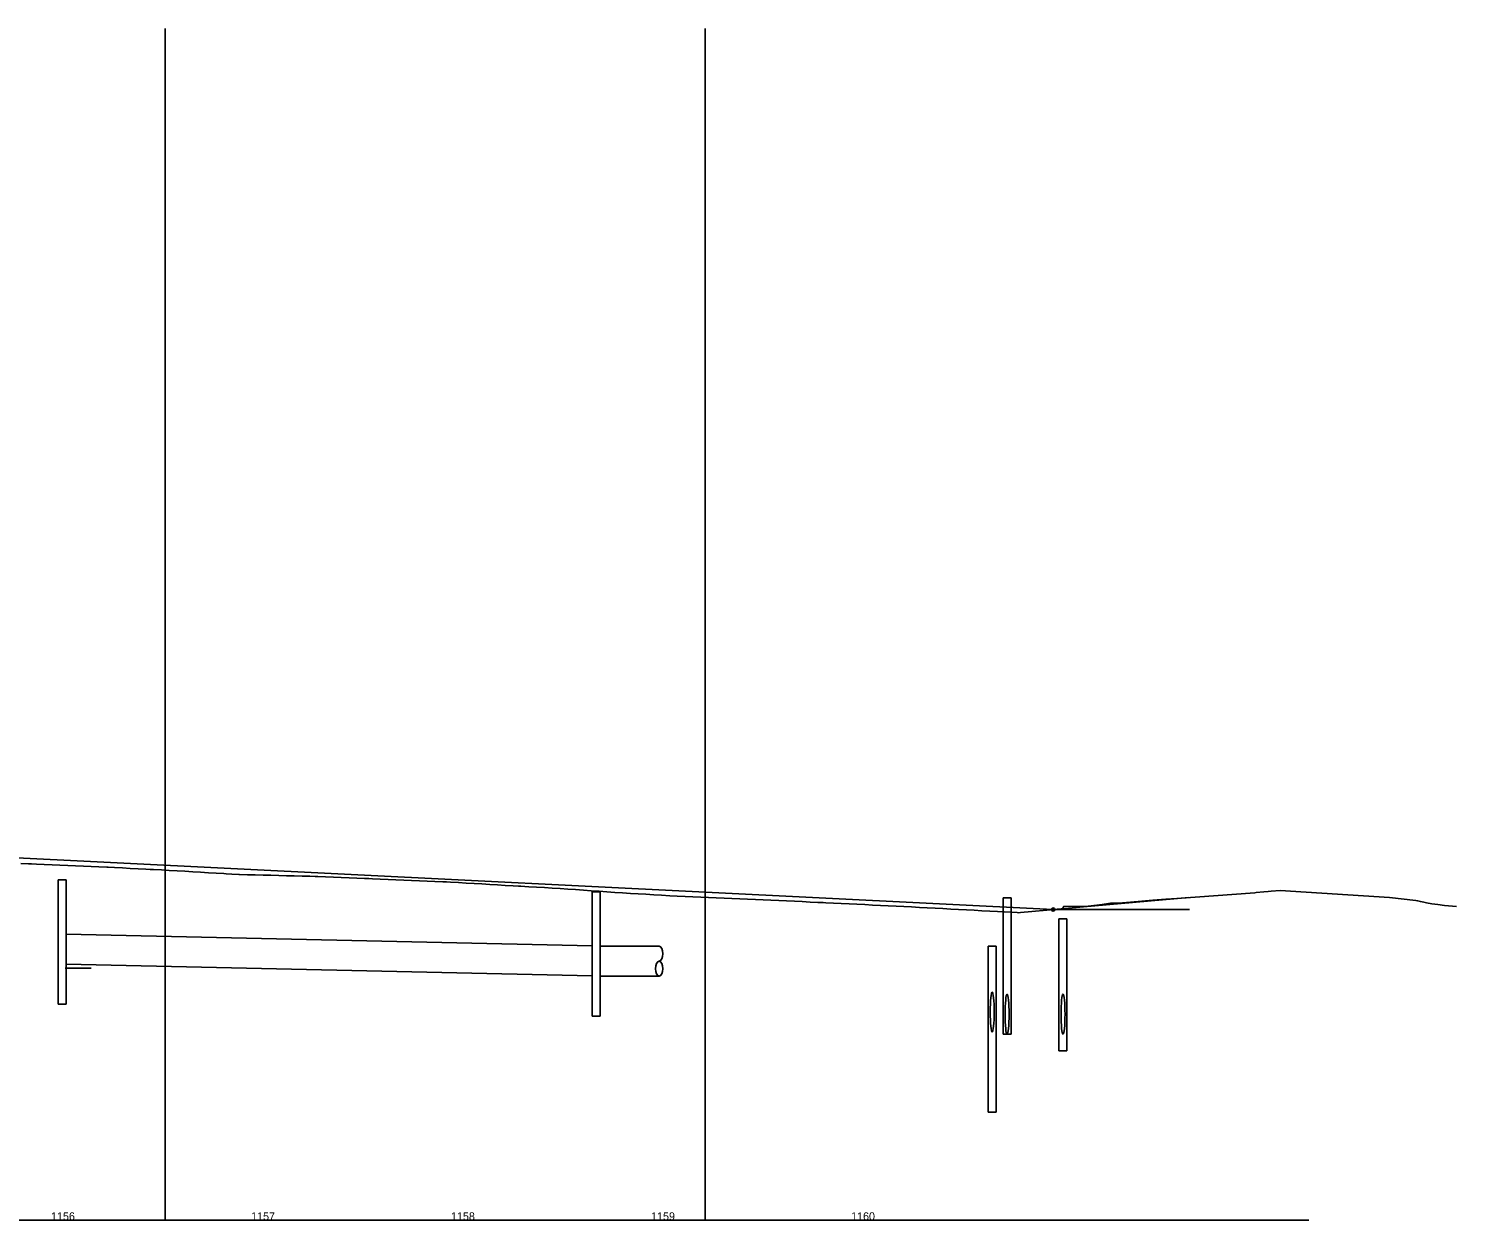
# Model space of a CAD drawing. Extents: x 1409 to 6106, y -2180 to -1584.
# Drawn here: x 5392 to 6106, y -2180 to -1584 of the extents above; entities that cross this region are included whole.
import ezdxf

# ---------------------------------------------------------------- set-up
doc = ezdxf.new("R2010")
doc.units = 0
for name, color, linetype in [('CLConst_dp', 7, 'Continuous'), ('DrainStruct_ex', 7, 'Continuous'), ('DrainStruct_pr', 7, 'Continuous'), ('NonPlottingEle_dp', 7, 'Continuous'), ('PipeCulvert_ex', 7, 'Continuous'), ('PipeCulvert_pr', 7, 'Continuous'), ('PipeCulvert_px', 7, 'Continuous'), ('StationTicS_dp', 7, 'Continuous'), ('TextLabel', 7, 'Continuous'), ('TextProfLabel', 7, 'Continuous'), ('TextPtLabel', 7, 'Continuous')]:
    doc.layers.add(name, color=color, linetype=linetype)

msp = doc.modelspace()

# ---------------------------------------------------------------- linework, layer by layer
at = {"layer": 'CLConst_dp'}
msp.add_line((1410.73, -2179.71), (6032.47, -2179.71), dxfattribs=at)
at = {"layer": 'DrainStruct_ex'}
for p, q in [((5907.5, -2047.25), (5907.5, -2094.97)), ((5911.5, -2047.25), (5911.5, -2094.97)), ((5907.5, -2094.97), (5911.5, -2094.97))]:
    msp.add_line(p, q, dxfattribs=at)
at = {"layer": 'DrainStruct_pr'}
for p, q in [((5407.29, -2009.51), (5411.29, -2009.51)), ((5407.29, -2009.51), (5407.29, -2071.71)), ((5411.29, -2009.51), (5411.29, -2071.71)), ((5674.18, -2015.59), (5678.18, -2015.59)), ((5674.18, -2015.59), (5674.18, -2077.69)), ((5678.18, -2015.59), (5678.18, -2077.69)), ((5879.68, -2018.61), (5883.68, -2018.61)), ((5879.68, -2018.61), (5879.68, -2033.15)), ((5883.68, -2018.61), (5883.68, -2033.15)), ((5907.5, -2029.01), (5911.5, -2029.01)), ((5907.5, -2029.01), (5907.5, -2047.25)), ((5911.5, -2029.01), (5911.5, -2047.25)), ((5872.18, -2042.71), (5876.18, -2042.71)), ((5872.18, -2042.71), (5872.18, -2125.71)), ((5876.18, -2042.71), (5876.18, -2125.71)), ((5407.29, -2071.71), (5411.29, -2071.71)), ((5674.18, -2077.69), (5678.18, -2077.69))]:
    msp.add_line(p, q, dxfattribs=at)
at = {"layer": 'NonPlottingEle_dp'}
msp.add_circle((5904.73, -2024.41), 0.8, dxfattribs=at)
at = {"layer": 'PipeCulvert_ex'}
for p, q in [((5879.68, -2018.61), (5883.68, -2018.61)), ((5879.68, -2018.61), (5879.68, -2086.71)), ((5883.68, -2018.61), (5883.68, -2086.71)), ((5879.68, -2086.71), (5883.68, -2086.71))]:
    msp.add_line(p, q, dxfattribs=at)
for centre in [(5881.68, -2076.71), (5909.63, -2076.71)]:
    msp.add_ellipse(centre, major_axis=(0, -10), ratio=0.1, dxfattribs=at)
at = {"layer": 'PipeCulvert_pr'}
for p, q in [((5674.18, -2042.61), (5411.29, -2036.68)), ((5678.18, -2042.71), (5707.71, -2042.71)), ((5674.18, -2057.61), (5411.29, -2051.68)), ((5678.18, -2057.71), (5707.71, -2057.71)), ((5876.18, -2125.71), (5872.18, -2125.71))]:
    msp.add_line(p, q, dxfattribs=at)
at = {"layer": 'PipeCulvert_px'}
msp.add_ellipse((5707.71, -2046.46), major_axis=(0, 3.75), ratio=0.5, start_param=3.141593, end_param=6.283185, dxfattribs=at)
for centre, major_axis, ratio in [((5707.71, -2053.96), (0, 3.75), 0.5), ((5874.23, -2075.62), (0, -10), 0.1)]:
    msp.add_ellipse(centre, major_axis=major_axis, ratio=ratio, dxfattribs=at)
at = {"layer": 'StationTicS_dp'}
for points in [[(5388.57, -2001.4), (5392.48, -2001.54), (5393.95, -2001.59), (5396.39, -2001.69), (5400.29, -2001.86), (5404.2, -2002.03), (5408.11, -2002.2), (5412.01, -2002.38), (5415.92, -2002.55), (5419.83, -2002.73), (5423.73, -2002.91), (5427.64, -2003.09), (5431.55, -2003.27), (5432.25, -2003.3), (5435.45, -2003.46), (5439.36, -2003.64), (5443.27, -2003.83), (5447.17, -2004.02), (5451.08, -2004.21), (5453.26, -2004.32), (5454.99, -2004.41), (5458.9, -2004.63), (5462.8, -2004.86), (5466.71, -2005.08), (5470.62, -2005.3), (5474.52, -2005.53), (5478.43, -2005.76), (5482.34, -2005.99), (5486.24, -2006.23), (5490.15, -2006.46), (5491.24, -2006.53), (5494.06, -2006.71), (5497.54, -2006.94), (5497.96, -2006.95), (5501.87, -2007.03), (5505.78, -2007.12), (5509.68, -2007.21), (5513.59, -2007.3), (5517.5, -2007.4), (5521.41, -2007.5), (5525.31, -2007.59), (5529.22, -2007.7), (5533.13, -2007.8), (5535.72, -2007.87), (5537.03, -2007.92), (5540.94, -2008.07), (5544.85, -2008.22), (5548.75, -2008.37), (5552.66, -2008.53), (5556.57, -2008.68), (5560.47, -2008.84), (5562.6, -2008.93), (5564.38, -2009), (5568.29, -2009.16), (5572.19, -2009.33), (5576.1, -2009.49), (5580.01, -2009.66), (5583.92, -2009.83), (5587.82, -2010), (5591.73, -2010.18), (5595.64, -2010.35), (5599.54, -2010.53), (5601.48, -2010.62), (5603.45, -2010.73), (5607.36, -2010.95), (5611.26, -2011.17), (5615.17, -2011.39), (5619.08, -2011.62), (5622.98, -2011.85), (5626.89, -2012.08), (5630.8, -2012.31), (5634.7, -2012.54), (5637.44, -2012.71), (5638.61, -2012.77), (5642.52, -2013), (5646.43, -2013.23), (5650.33, -2013.46), (5654.24, -2013.7), (5658.15, -2013.93), (5662.05, -2014.17), (5665.97, -2014.41), (5669.87, -2014.69), (5673.77, -2014.97), (5677.68, -2015.25), (5681.59, -2015.54), (5685.49, -2015.83), (5689.4, -2016.12), (5693.31, -2016.34), (5697.21, -2016.56), (5701.12, -2016.79), (5705.03, -2017.02), (5708.93, -2017.25), (5713.08, -2017.5), (5716.75, -2017.65), (5720.66, -2017.82), (5724.56, -2017.98), (5728.47, -2018.15), (5732.38, -2018.32), (5736.28, -2018.49), (5740.19, -2018.66), (5744.1, -2018.84), (5748, -2019.01), (5751.91, -2019.19), (5755.82, -2019.36), (5759.72, -2019.54), (5763.63, -2019.72), (5767.54, -2019.9), (5771.44, -2020.09), (5775.35, -2020.27), (5779.26, -2020.45), (5783.17, -2020.64), (5787.07, -2020.83), (5789.64, -2020.95), (5790.98, -2021.02), (5794.89, -2021.2), (5798.79, -2021.39), (5802.7, -2021.58), (5806.61, -2021.77), (5810.51, -2021.96), (5814.42, -2022.15), (5818.33, -2022.34), (5822.23, -2022.54), (5826.14, -2022.74), (5830.05, -2022.93), (5833.95, -2023.13), (5837.86, -2023.33), (5841.77, -2023.53), (5845.68, -2023.74), (5849.58, -2023.94), (5853.49, -2024.15), (5857.4, -2024.35), (5861.3, -2024.56), (5865.21, -2024.77), (5869.12, -2024.98), (5873.02, -2025.19), (5876.93, -2025.4), (5886.68, -2025.94), (5887.46, -2025.99), (5888.33, -2025.91), (5907.14, -2024.21), (5907.98, -2024.16), (5908.5, -2024.15), (5909.1, -2024.16), (5909.44, -2024.1), (5912.48, -2023.74), (5922.28, -2022.65), (5923.75, -2022.51), (5929.26, -2021.84), (5933.4, -2021.25), (5939.37, -2021.02), (5947.24, -2020.33), (5954.58, -2019.73), (5961.08, -2019.23), (5966.61, -2018.84), (6005.48, -2015.98), (6006.18, -2015.93), (6010.04, -2015.49), (6012.24, -2015.31), (6013.62, -2015.26), (6018.25, -2014.81), (6072.84, -2018.4), (6085.98, -2019.88), (6086.96, -2020.12), (6088.31, -2020.41), (6090.09, -2020.76), (6091.4, -2021.03), (6093.97, -2021.49), (6097.01, -2021.94), (6100.4, -2022.35), (6106.33, -2022.86)], [(5388.57, -2001.4), (5392.48, -2001.54), (5393.95, -2001.59), (5396.39, -2001.69), (5400.29, -2001.86), (5404.2, -2002.03), (5408.11, -2002.2), (5412.01, -2002.38), (5415.92, -2002.55), (5419.83, -2002.73), (5423.73, -2002.91), (5427.64, -2003.09), (5431.55, -2003.27), (5432.25, -2003.3), (5435.45, -2003.46), (5439.36, -2003.64), (5443.27, -2003.83), (5447.17, -2004.02), (5451.08, -2004.21), (5453.26, -2004.32), (5454.99, -2004.41), (5458.9, -2004.63), (5462.8, -2004.86), (5466.71, -2005.08), (5470.62, -2005.3), (5474.52, -2005.53), (5478.43, -2005.76), (5482.34, -2005.99), (5486.24, -2006.23), (5490.15, -2006.46), (5491.24, -2006.53), (5494.06, -2006.71), (5497.54, -2006.94), (5497.96, -2006.95), (5501.87, -2007.03), (5505.78, -2007.12), (5509.68, -2007.21), (5513.59, -2007.3), (5517.5, -2007.4), (5521.41, -2007.5), (5525.31, -2007.59), (5529.22, -2007.7), (5533.13, -2007.8), (5535.72, -2007.87), (5537.03, -2007.92), (5540.94, -2008.07), (5544.85, -2008.22), (5548.75, -2008.37), (5552.66, -2008.53), (5556.57, -2008.68), (5560.47, -2008.84), (5562.6, -2008.93), (5564.38, -2009), (5568.29, -2009.16), (5572.19, -2009.33), (5576.1, -2009.49), (5580.01, -2009.66), (5583.92, -2009.83), (5587.82, -2010), (5591.73, -2010.18), (5595.64, -2010.35), (5599.54, -2010.53), (5601.48, -2010.62), (5603.45, -2010.73), (5607.36, -2010.95), (5611.26, -2011.17), (5615.17, -2011.39), (5619.08, -2011.62), (5622.98, -2011.85), (5626.89, -2012.08), (5630.8, -2012.31), (5634.7, -2012.54), (5637.44, -2012.71), (5638.61, -2012.77), (5642.52, -2013), (5646.43, -2013.23), (5650.33, -2013.46), (5654.24, -2013.7), (5658.15, -2013.93), (5662.05, -2014.17), (5665.97, -2014.41), (5669.87, -2014.69), (5673.77, -2014.97), (5677.68, -2015.25), (5681.59, -2015.54), (5685.49, -2015.83), (5689.4, -2016.12), (5693.31, -2016.34), (5697.21, -2016.56), (5701.12, -2016.79), (5705.03, -2017.02), (5708.93, -2017.25), (5713.08, -2017.5), (5716.75, -2017.65), (5720.66, -2017.82), (5724.56, -2017.98), (5728.47, -2018.15), (5732.38, -2018.32), (5736.28, -2018.49), (5740.19, -2018.66), (5744.1, -2018.84), (5748, -2019.01), (5751.91, -2019.19), (5755.82, -2019.36), (5759.72, -2019.54), (5763.63, -2019.72), (5767.54, -2019.9), (5771.44, -2020.09), (5775.35, -2020.27), (5779.26, -2020.45), (5783.17, -2020.64), (5787.07, -2020.83), (5789.64, -2020.95), (5790.98, -2021.02), (5794.89, -2021.2), (5798.79, -2021.39), (5802.7, -2021.58), (5806.61, -2021.77), (5810.51, -2021.96), (5814.42, -2022.15), (5818.33, -2022.34), (5822.23, -2022.54), (5826.14, -2022.74), (5830.05, -2022.93), (5833.95, -2023.13), (5837.86, -2023.33), (5841.77, -2023.53), (5845.68, -2023.74), (5849.58, -2023.94), (5853.49, -2024.15), (5857.4, -2024.35), (5861.3, -2024.56), (5865.21, -2024.77), (5869.12, -2024.98), (5873.02, -2025.19), (5876.93, -2025.4), (5886.68, -2025.94), (5887.46, -2025.99), (5888.33, -2025.91), (5907.14, -2024.21), (5907.98, -2024.16), (5908.5, -2024.15), (5909.1, -2024.16), (5909.44, -2024.1), (5910, -2022.83), (5922.28, -2022.65), (5923.75, -2022.51), (5929.26, -2021.84), (5933.4, -2021.25), (5939.37, -2021.02), (5947.24, -2020.33), (5954.58, -2019.73), (5961.08, -2019.23), (5966.61, -2018.84), (6005.48, -2015.98), (6006.18, -2015.93), (6010.04, -2015.49), (6012.24, -2015.31), (6013.62, -2015.26), (6018.25, -2014.81), (6072.84, -2018.4), (6085.98, -2019.88), (6086.96, -2020.12), (6088.31, -2020.41), (6090.09, -2020.76), (6091.4, -2021.03), (6093.97, -2021.49), (6097.01, -2021.94), (6100.4, -2022.35), (6106.33, -2022.86)]]:
    msp.add_lwpolyline(points, dxfattribs=at)
at = {"layer": 'TextLabel'}
for p, q in [((5460.73, -2179.71), (5460.73, -1584.14)), ((5730.73, -2179.71), (5730.73, -1584.14)), ((5904.82, -2024.42), (5972.53, -2018.41)), ((5904.82, -2024.42), (5972.8, -2024.42)), ((5410.72, -2053.71), (5423.67, -2053.71))]:
    msp.add_line(p, q, dxfattribs=at)
at = {"layer": 'TextPtLabel'}
msp.add_line((5320.73, -1995.21), (5904.73, -2024.41), dxfattribs=at)

# ---------------------------------------------------------------- texts
at = {"layer": 'TextProfLabel'}
for s, p in [('1156', (5403.71, -2179.71)), ('1157', (5503.75, -2179.71)), ('1158', (5603.68, -2179.71)), ('1159', (5703.71, -2179.71)), ('1160', (5803.71, -2179.71))]:
    msp.add_text(s, height=4, dxfattribs=at).set_placement(p)

doc.saveas('drawing.dxf')
